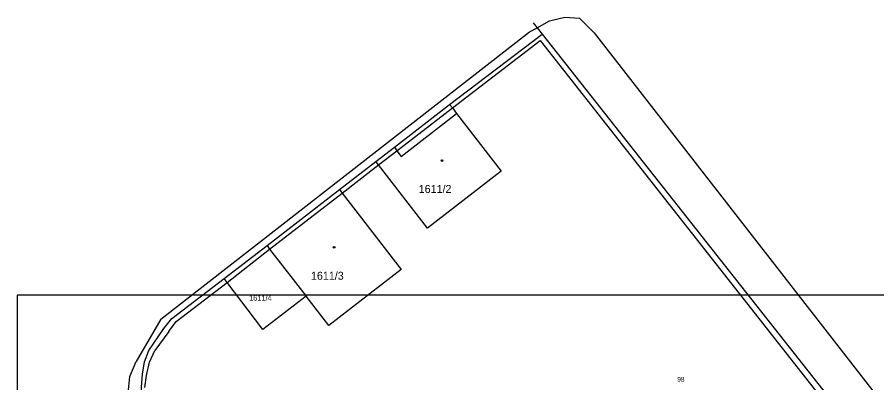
# Model space of a CAD drawing. Extents: x -600587 to -600377, y -1159886 to -1159708.
# Drawn here: x -600586.6 to -600495.4, y -1159747.2 to -1159708.3 of the extents above; entities that cross this region are included whole.
import ezdxf

# ---------------------------------------------------------------- set-up
doc = ezdxf.new("R2010")
doc.units = 0
for name, color, linetype in [('Hranice parcel', 7, 'Continuous'), ('Parcelní čísla', 7, 'Continuous'), ('Vnitřní kresba', 7, 'Continuous'), ('Vrstva 2', 7, 'Continuous'), ('Vrstva 59', 7, 'Continuous'), ('Značky budov', 7, 'Continuous')]:
    doc.layers.add(name, color=color, linetype=linetype)

msp = doc.modelspace()

# ---------------------------------------------------------------- linework, layer by layer
at = {"layer": 'Hranice parcel'}
for p, q in [((-600540.75, -1159717.59), (-600530.91, -1159710.13)), ((-600552.4, -1159726.63), (-600548.56, -1159723.65)), ((-600560.1, -1159732.57), (-600552.4, -1159726.63)), ((-600564.67, -1159736.09), (-600560.1, -1159732.57))]:
    msp.add_line(p, q, dxfattribs=at)
for points in [[(-600531.832, -1159708.922), (-600531.43, -1159709.45), (-600530.91, -1159710.13)], [(-600530.91, -1159710.13), (-600493.42, -1159757.63), (-600491.23, -1159760.48), (-600448.05, -1159816.59)], [(-600548.56, -1159723.65), (-600546.58, -1159722.14), (-600540.75, -1159717.59)], [(-600540.75, -1159717.59), (-600540.43, -1159717.97), (-600539.99, -1159718.56), (-600535.26, -1159724.68), (-600543.07, -1159730.73), (-600548.27, -1159724.02), (-600548.56, -1159723.65)], [(-600552.4, -1159726.63), (-600552.13, -1159727.02), (-600545.85, -1159735.12), (-600553.53, -1159741.07), (-600555.94, -1159737.96)], [(-600560.1, -1159732.57), (-600559.83, -1159732.97), (-600555.94, -1159737.96)], [(-600488.61, -1159847.98), (-600490.62, -1159848.62), (-600491.99, -1159848.82), (-600493.39, -1159848.77), (-600494.93, -1159848.62), (-600496.36, -1159848.13), (-600500.23, -1159845.75), (-600572.32, -1159752.89), (-600572.98, -1159751.48), (-600573.33, -1159750.24), (-600573.44, -1159748.95), (-600573.44, -1159747.6), (-600573.32, -1159746.25), (-600573.13, -1159744.93), (-600572.66, -1159743.72), (-600571.05, -1159741.4), (-600570.22, -1159740.33), (-600564.67, -1159736.09)], [(-600555.94, -1159737.96), (-600560.55, -1159741.48), (-600564.35, -1159736.51), (-600564.67, -1159736.09)]]:
    msp.add_lwpolyline(points, dxfattribs=at)
at = {"layer": 'Vnitřní kresba'}
for p, q in [((-600531.43, -1159709.45), (-600530.1, -1159708.71)), ((-600530.1, -1159708.71), (-600528.47, -1159708.33)), ((-600528.47, -1159708.33), (-600526.93, -1159708.44)), ((-600526.93, -1159708.44), (-600525.36, -1159709.98)), ((-600571.38, -1159740.41), (-600532.25, -1159709.9)), ((-600532.25, -1159709.9), (-600531.43, -1159709.45)), ((-600525.36, -1159709.98), (-600494.19, -1159750.03)), ((-600540.43, -1159717.97), (-600531.09, -1159710.8)), ((-600531.09, -1159710.8), (-600493.91, -1159758.06)), ((-600546.31, -1159722.51), (-600540.43, -1159717.97)), ((-600545.86, -1159723.14), (-600539.99, -1159718.56)), ((-600548.27, -1159724.02), (-600546.31, -1159722.51)), ((-600546.58, -1159722.14), (-600546.31, -1159722.51)), ((-600546.31, -1159722.51), (-600545.86, -1159723.14)), ((-600552.13, -1159727.02), (-600548.27, -1159724.02)), ((-600559.83, -1159732.97), (-600552.13, -1159727.02)), ((-600564.35, -1159736.51), (-600559.83, -1159732.97)), ((-600569.76, -1159740.63), (-600564.35, -1159736.51)), ((-600571.38, -1159740.41), (-600574.02, -1159744.89)), ((-600570.55, -1159741.7), (-600569.76, -1159740.63)), ((-600570.55, -1159741.7), (-600572.01, -1159743.72)), ((-600572.6, -1159744.98), (-600572.01, -1159743.72)), ((-600574.69, -1159746.5), (-600574.02, -1159744.89)), ((-600572.91, -1159746.37), (-600572.6, -1159744.98)), ((-600574.86, -1159748.24), (-600574.69, -1159746.5)), ((-600573.07, -1159747.65), (-600572.91, -1159746.37))]:
    msp.add_line(p, q, dxfattribs=at)
at = {"layer": 'Vrstva 2'}
msp.add_lwpolyline([(-600586.635, -1159886.355), (-600376.635, -1159886.355), (-600376.635, -1159737.855), (-600586.635, -1159737.855)], close=True, dxfattribs=at)
at = {"layer": 'Značky budov'}
for centre in [(-600541.533, -1159723.55), (-600552.983, -1159732.76)]:
    msp.add_circle(centre, 0.0875, dxfattribs=at)

# ---------------------------------------------------------------- texts
at = {"layer": 'Parcelní čísla'}
for s, height, p in [('1611/2', 0.85, (-600544.001, -1159727)), ('1611/3', 0.85, (-600555.444, -1159736.21)), ('1611/4', 0.5695, (-600562.013, -1159738.429))]:
    msp.add_text(s, height=height, dxfattribs=at).set_placement(p)
at = {"layer": 'Vrstva 59'}
msp.add_text('98', height=0.5, dxfattribs=at).set_placement((-600516.549, -1159747.031))

doc.saveas('drawing.dxf')
